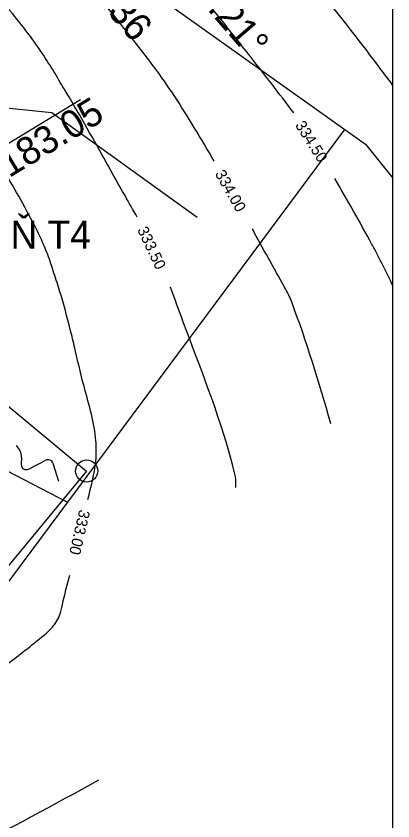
# Model space of a CAD drawing. Extents: x -564037 to -563827, y -1163561 to -1163412.
# Drawn here: x -563843.49 to -563826.51, y -1163524.35 to -1163488.1 of the extents above; entities that cross this region are included whole.
import ezdxf

# ---------------------------------------------------------------- set-up
doc = ezdxf.new("R2010")
doc.units = 0
for name, color, linetype in [('4', 7, 'Continuous'), ('5', 7, 'Continuous'), ('_popis staničení RT1', 7, 'Continuous'), ('_rám RT1', 7, 'Continuous'), ('Hranice parcel', 7, 'Continuous'), ('Obvod PU', 7, 'Continuous'), ('podélný profil', 7, 'Continuous'), ('Vrstva 24', 7, 'Continuous'), ('Vrstva 25', 7, 'Continuous'), ('Vrstva 26', 7, 'Continuous')]:
    doc.layers.add(name, color=color, linetype=linetype)

msp = doc.modelspace()

# ---------------------------------------------------------------- linework, layer by layer
msp.add_lwpolyline([(-563835.323, -1163497.175), (-563841.877, -1163492.459), (-563849.248, -1163491.704)])
at = {"layer": '5'}
for p, q in [((-563871.424, -1163494.398), (-563841.172, -1163509.993)), ((-563845.378, -1163504.4), (-563840.311, -1163508.591))]:
    msp.add_line(p, q, dxfattribs=at)
at = {"layer": '_popis staničení RT1'}
for points in [[(-563840.579, -1163491.879), (-563850.828, -1163498.085)], [(-563840.311, -1163508.591), (-563849.872, -1163520.149)]]:
    msp.add_lwpolyline(points, dxfattribs=at)
msp.add_circle((-563840.311, -1163508.591), 0.5, dxfattribs=at)
at = {"layer": '_rám RT1'}
msp.add_line((-563826.505, -1163560.994), (-563826.505, -1163412.494), dxfattribs=at)
at = {"layer": 'Hranice parcel'}
msp.add_lwpolyline([(-564028.91, -1163536.42), (-563982.72, -1163544.1), (-563870.61, -1163549.59), (-563828.67, -1163493.21)], dxfattribs=at)
at = {"layer": 'Obvod PU'}
msp.add_line((-563837.86, -1163486.67), (-563828.67, -1163493.21), dxfattribs=at)
msp.add_lwpolyline([(-563828.67, -1163493.21), (-563827.74, -1163493.87), (-563826.505, -1163495.405)], dxfattribs=at)
at = {"layer": 'podélný profil'}
for points in [[(-563843.245, -1163507.989), (-563843.253, -1163508.296)], [(-563842.925, -1163508.503), (-563842.15, -1163508.107)], [(-563841.833, -1163508.239), (-563841.571, -1163509.049)]]:
    msp.add_lwpolyline(points, dxfattribs=at)
for centre, radius, start, end in [((-563843.922, -1163507.971), 0.677, 358.5156, 50.2101), ((-563843.028, -1163508.302), 0.226, 178.5177, 297.0647), ((-563842.047, -1163508.308), 0.226, 17.9212, 117.0384)]:
    msp.add_arc(centre, radius, start, end, dxfattribs=at)
at = {"layer": 'Vrstva 24'}
for points in [[(-563834.56, -1163494.639), (-563836.366, -1163491.682), (-563837.263, -1163490.402), (-563838.091, -1163489.323), (-563838.932, -1163488.255), (-563840.679, -1163486.176), (-563843.599, -1163482.931), (-563845.377, -1163480.993), (-563847.69, -1163478.523), (-563848.871, -1163477.312), (-563850.082, -1163476.13), (-563853.183, -1163473.259), (-563856.324, -1163470.434), (-563856.74, -1163470.064), (-563856.896, -1163469.927), (-563857.179, -1163469.672), (-563858.782, -1163468.194), (-563860.374, -1163466.704), (-563861.969, -1163465.217), (-563862.806, -1163464.448)], [(-563840.258, -1163509.873), (-563839.896, -1163508.143), (-563839.904, -1163507.091), (-563840.452, -1163504.683), (-563840.841, -1163503.06), (-563841.044, -1163502.221), (-563841.512, -1163500.521), (-563841.78, -1163499.679), (-563842.064, -1163498.842), (-563842.395, -1163498.068), (-563843.845, -1163495.39), (-563845.853, -1163491.78), (-563846.807, -1163490.032), (-563847.876, -1163488.404), (-563852.123, -1163483.19), (-563853.868, -1163481.341), (-563857.18, -1163478.245), (-563858.504, -1163477.011), (-563860.386, -1163475.26)], [(-563829.3, -1163506.46), (-563831.082, -1163500.946), (-563831.21, -1163500.638), (-563831.385, -1163500.313), (-563832.841, -1163497.687)], [(-563878.638, -1163525.959), (-563876.035, -1163525.73), (-563873.358, -1163525.577), (-563872.019, -1163525.506), (-563870.681, -1163525.42), (-563867.228, -1163525.059), (-563863.791, -1163524.486), (-563862.262, -1163524.199), (-563857.791, -1163523.308), (-563852.826, -1163522.134), (-563851.58, -1163521.769), (-563850.041, -1163521.109), (-563844.975, -1163518.031), (-563844.52, -1163517.734), (-563844.289, -1163517.571), (-563843.081, -1163516.667), (-563842.493, -1163516.19), (-563841.914, -1163515.69), (-563841.532, -1163515.102), (-563841.398, -1163514.605), (-563841.069, -1163513.278)]]:
    msp.add_spline(points, degree=3, dxfattribs=at)
at = {"layer": 'Vrstva 25'}
msp.add_spline([(-563826.505, -1163491.224), (-563828.382, -1163488.752), (-563832.28, -1163483.99)], degree=3, dxfattribs=at)
at = {"layer": 'Vrstva 26'}
for points in [[(-563838.029, -1163497.163), (-563838.58, -1163496.19), (-563840.28, -1163493.165), (-563841.199, -1163491.578), (-563841.674, -1163490.793), (-563842.159, -1163490.013), (-563843.649, -1163487.993), (-563844.702, -1163486.757), (-563850.461, -1163480.038), (-563851.089, -1163479.371), (-563851.956, -1163478.574), (-563857.613, -1163473.501), (-563859.731, -1163471.636), (-563864.022, -1163468.083), (-563864.562, -1163467.631), (-563865.045, -1163467.216), (-563865.679, -1163466.68)], [(-563830.975, -1163492.455), (-563831.969, -1163491.156), (-563833.366, -1163489.371), (-563836.213, -1163485.841), (-563837.542, -1163484.256), (-563839.463, -1163482.209), (-563842.521, -1163479.096), (-563847.489, -1163473.999), (-563848.959, -1163472.514), (-563850.05, -1163471.5)], [(-563826.505, -1163500.248), (-563826.968, -1163499.295), (-563827.212, -1163498.825), (-563827.463, -1163498.359), (-563828.283, -1163496.883), (-563829.116, -1163495.416)], [(-563833.59, -1163509.33), (-563833.604, -1163508.852), (-563833.629, -1163508.738), (-563835.951, -1163501.89), (-563836.525, -1163500.318)], [(-563872.722, -1163529.939), (-563871.679, -1163529.88), (-563868.423, -1163529.658), (-563863.398, -1163529.309), (-563855.833, -1163528.593), (-563855.067, -1163528.505), (-563854.672, -1163528.45), (-563853.844, -1163528.268), (-563848.691, -1163526.867), (-563847.963, -1163526.628), (-563847.244, -1163526.363), (-563845.853, -1163525.73), (-563839.76, -1163522.5)]]:
    msp.add_spline(points, degree=3, dxfattribs=at)

# ---------------------------------------------------------------- texts
at = {"layer": '4'}
msp.add_text('TŮŇ T4', height=1.25, rotation=360, dxfattribs=at).set_placement((-563845.97, -1163498.57))
at = {"layer": '_popis staničení RT1'}
for s, rotation, p in [('R=25m alfa=19.21%%d', 310.7988, (-563842.367, -1163479.147)), ('   z=0.36', 310.7988, (-563842.417, -1163484.446)), ('0+183.05', 31.1947, (-563845.435, -1163496.392))]:
    msp.add_text(s, height=1.25, rotation=rotation, dxfattribs=at).set_placement(p)
at = {"layer": 'Vrstva 25'}
for s, rotation, p in [('334.50', 302.235, (-563830.931, -1163493.012)), ('334.00', 299.5928, (-563834.542, -1163495.199)), ('333.50', 295.4127, (-563838.04, -1163497.723)), ('333.00', 256.8372, (-563840.634, -1163510.303))]:
    msp.add_text(s, height=0.5, rotation=rotation, dxfattribs=at).set_placement(p)

doc.saveas('drawing.dxf')
